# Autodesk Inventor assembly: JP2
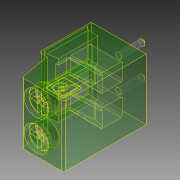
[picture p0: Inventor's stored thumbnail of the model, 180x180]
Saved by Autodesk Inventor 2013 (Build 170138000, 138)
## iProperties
Created: 2021-02
Part Number: JP2
Document SubType Name: Assembly
Designer: Fede
Author: Fede
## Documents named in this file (2)
- C:\0000 FEDE\16GB\0000 INTERIOR\DE_TMP_BAS\BAS_DTON - demora conexion al energizar\DTON_MANUAL\img\INVENTOR\BAS_DTON - SIN R\JP2.iam
- C:\0000 FEDE\16GB\0000 INTERIOR\DE_TMP_BAS\BAS_DTON - demora conexion al energizar\DTON_MANUAL\img\INVENTOR\BAS_DTON - SIN R\bornera2x1.iam
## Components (1 placed, 1 different names)
1. bornera2x1:1 [sub-assembly]
